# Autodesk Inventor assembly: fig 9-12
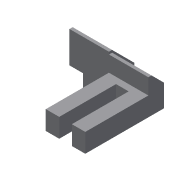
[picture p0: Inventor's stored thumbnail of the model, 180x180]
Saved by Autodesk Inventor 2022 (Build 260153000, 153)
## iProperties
Created: 2002-01
Part Number: fig 9-12
Document SubType Name: Assembly
Designer: ***
Control State: 0
Master: False
Checked Out: False
Shininess: 64.0
Length Units: 11269
Angle Units: 11279
Time Units: 11290
Mass Units: 11283
Length Display Precision: 3
Angle Display Precision: 2
Density: 0.0
Volumn: 0.0
Area: 0.0
PropertySet Name: Model Information
Author: ***
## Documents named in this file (3)
- D:\PROJECTS_2021\Resources\Part Files\c09_Inv_2022_prt\fig 9-12.iam
- D:\PROJECTS_2021\Resources\Part Files\c09_Inv_2022_prt\Part3.ipt
- D:\PROJECTS_2021\Resources\Part Files\c09_Inv_2022_prt\Part4.ipt
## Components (2 placed, 2 different names)
1. Part3:1 — Flush:1, Flush:2, Flush:3, Mate:1
2. Part4:1 — Flush:1, Flush:2, Flush:3, Mate:1
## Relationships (4: Flush 3, Mate 1)
- Flush:1: Part3:1 ↔ Part4:1
- Flush:2: Part3:1 ↔ Part4:1
- Flush:3: Part3:1 ↔ Part4:1
- Mate:1: Part3:1 ↔ Part4:1
